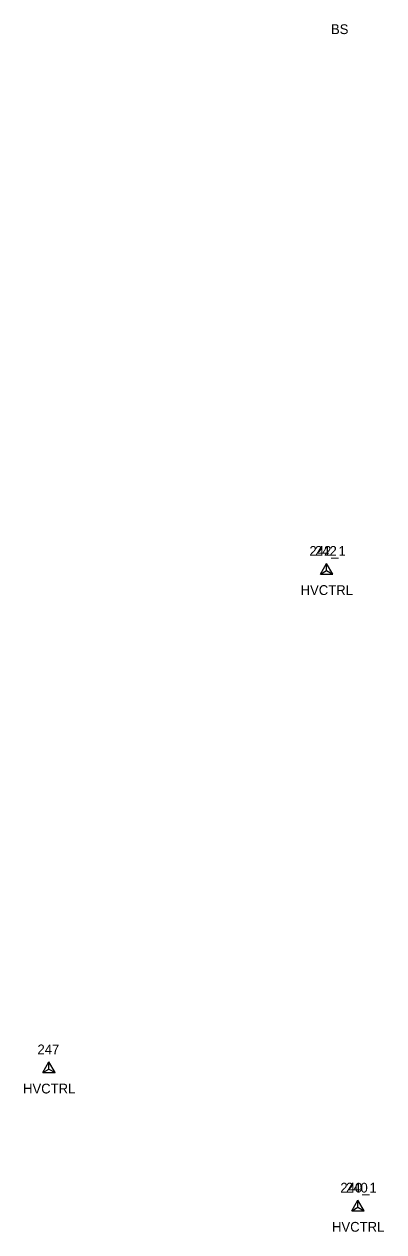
# Model space of a CAD drawing. Extents: x 1769141 to 1770817, y 735471 to 742405.
# Drawn here: x 1770146.9 to 1770220.5, y 740081.9 to 740328.7 of the extents above; entities that cross this region are included whole.
import ezdxf

# ---------------------------------------------------------------- set-up
doc = ezdxf.new("R2010")
doc.units = 0
for name, color, linetype in [('C_A', 7, 'Continuous'), ('C_I', 7, 'Continuous'), ('CPSM', 7, 'Continuous'), ('L_A', 7, 'Continuous')]:
    doc.layers.add(name, color=color, linetype=linetype)

msp = doc.modelspace()

# ---------------------------------------------------------------- linework, layer by layer
at = {"layer": 'CPSM'}
for p, q in [((1770207.55, 740216.35), (1770208.8, 740218.52)), ((1770207.55, 740216.35), (1770208.8, 740218.52)), ((1770207.55, 740216.35), (1770208.8, 740217.07)), ((1770207.55, 740216.35), (1770208.8, 740217.07)), ((1770207.55, 740216.35), (1770210.05, 740216.35)), ((1770207.55, 740216.35), (1770210.05, 740216.35)), ((1770210.05, 740216.35), (1770208.8, 740218.52)), ((1770208.8, 740217.07), (1770208.8, 740218.52)), ((1770210.05, 740216.35), (1770208.8, 740218.52)), ((1770208.8, 740217.07), (1770208.8, 740218.52)), ((1770208.8, 740217.07), (1770208.8, 740217.07)), ((1770208.8, 740217.07), (1770210.05, 740216.35)), ((1770208.8, 740217.07), (1770208.8, 740217.07)), ((1770208.8, 740217.07), (1770210.05, 740216.35)), ((1770150.77, 740114.49), (1770152.02, 740116.65)), ((1770150.77, 740114.49), (1770152.02, 740115.21)), ((1770153.27, 740114.49), (1770152.02, 740116.65)), ((1770152.02, 740115.21), (1770152.02, 740116.65)), ((1770152.02, 740115.21), (1770152.02, 740115.21)), ((1770152.02, 740115.21), (1770153.27, 740114.49)), ((1770150.77, 740114.49), (1770153.27, 740114.49)), ((1770213.96, 740086.24), (1770215.21, 740088.41)), ((1770213.96, 740086.24), (1770215.21, 740088.41)), ((1770216.46, 740086.24), (1770215.21, 740088.41)), ((1770215.21, 740086.96), (1770215.21, 740088.41)), ((1770216.46, 740086.24), (1770215.21, 740088.41)), ((1770215.21, 740086.96), (1770215.21, 740088.41)), ((1770213.96, 740086.24), (1770215.21, 740086.96)), ((1770213.96, 740086.24), (1770215.21, 740086.96)), ((1770213.96, 740086.24), (1770216.46, 740086.24)), ((1770213.96, 740086.24), (1770216.46, 740086.24)), ((1770215.21, 740086.96), (1770215.21, 740086.96)), ((1770215.21, 740086.96), (1770216.46, 740086.24)), ((1770215.21, 740086.96), (1770215.21, 740086.96)), ((1770215.21, 740086.96), (1770216.46, 740086.24))]:
    msp.add_line(p, q, dxfattribs=at)

# ---------------------------------------------------------------- texts
at = {"layer": 'C_A'}
for p in [(1770203.49, 740212.07), (1770203.49, 740212.07), (1770146.71, 740110.21), (1770209.91, 740081.96), (1770209.91, 740081.96)]:
    msp.add_text('HVCTRL', height=2, dxfattribs=at).set_placement(p)
at = {"layer": 'C_I'}
for s, p in [('242_1', (1770205.29, 740220.07)), ('242', (1770206.43, 740220.07)), ('247', (1770149.66, 740118.21)), ('240_1', (1770211.62, 740089.96)), ('240', (1770212.76, 740089.96))]:
    msp.add_text(s, height=2, dxfattribs=at).set_placement(p)
at = {"layer": 'L_A'}
msp.add_text('BS', height=2, dxfattribs=at).set_placement((1770209.7, 740326.68))

doc.saveas('drawing.dxf')
